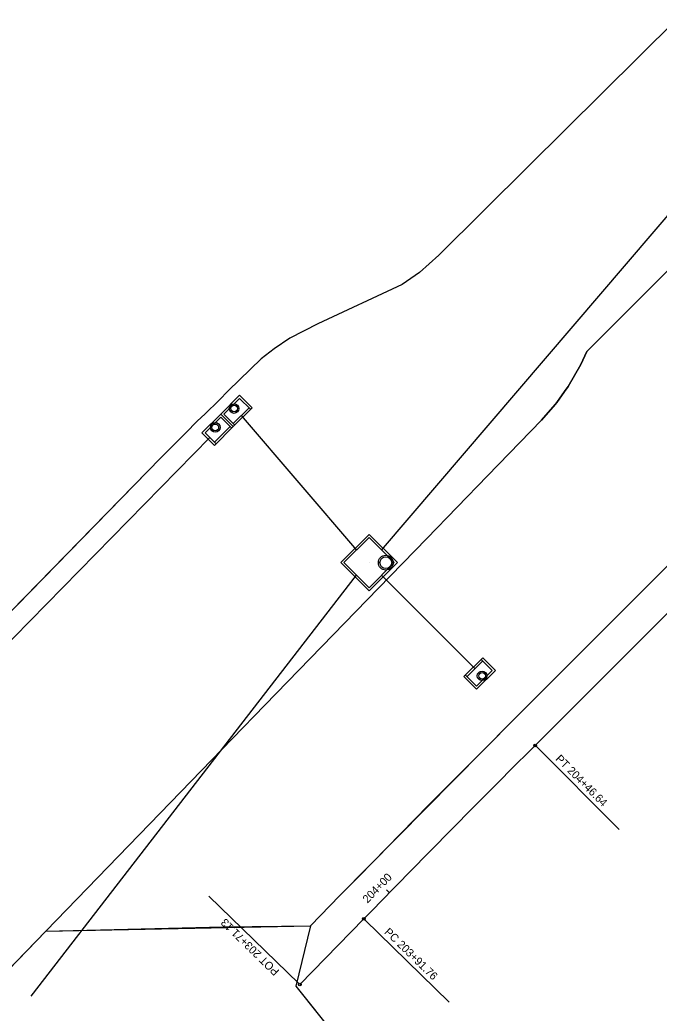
# Model space of a CAD drawing. Extents: x 2251012 to 2259557, y 13786786 to 13792525.
# Drawn here: x 2252898.1 to 2253042, y 13788698.7 to 13788922.1 of the extents above; entities that cross this region are included whole.
import ezdxf

# ---------------------------------------------------------------- set-up
doc = ezdxf.new("R2010")
doc.units = 0
for name, color, linetype in [('D_ALIGN_ANNO_1', 7, 'Continuous'), ('D_BOXES_1', 7, 'Continuous'), ('D_DRAIN_MISC', 7, 'Continuous'), ('D_DRN_AREA_A', 7, 'Continuous'), ('D_DRN_AREA_PHI', 7, 'Continuous'), ('D_DRN_AREA_X', 7, 'Continuous'), ('D_INLET_1', 7, 'Continuous'), ('D_PIPES_1', 7, 'Continuous'), ('Grade_DitchLine', 7, 'Continuous')]:
    doc.layers.add(name, color=color, linetype=linetype)

msp = doc.modelspace()

# ---------------------------------------------------------------- linework, layer by layer
at = {"layer": 'D_ALIGN_ANNO_1'}
for p, q in [((2253014.32, 13788758.7), (2253033.01, 13788739.98)), ((2252981.3, 13788725.76), (2252980.65, 13788726.39)), ((2252960.93, 13788705.3), (2252940.69, 13788725.01)), ((2252975.75, 13788719.65), (2252994.74, 13788701.16))]:
    msp.add_line(p, q, dxfattribs=at)
for centre in [(2253014.11, 13788758.91), (2252975.54, 13788719.86), (2252961.14, 13788705.09)]:
    msp.add_circle(centre, 0.3, dxfattribs=at)
at = {"layer": 'D_BOXES_1'}
for p, q in [((2252979.56, 13788802.85), (2253062.33, 13788899.63)), ((2252900.7, 13788702.47), (2252973.9, 13788797.2))]:
    msp.add_line(p, q, dxfattribs=at)
at = {"layer": 'D_DRAIN_MISC'}
for p, q in [((2252945.82, 13788835.23), (2252945.82, 13788835.23)), ((2252948.65, 13788835.93), (2252948.65, 13788835.93)), ((2252947.94, 13788833.1), (2252947.94, 13788833.1)), ((2252941.58, 13788830.99), (2252941.58, 13788830.99)), ((2252944.76, 13788832.04), (2252944.76, 13788832.04)), ((2252943.7, 13788828.86), (2252943.7, 13788828.86)), ((2252940.87, 13788828.16), (2252940.87, 13788828.16)), ((2252973.9, 13788802.85), (2252973.9, 13788802.85)), ((2252979.56, 13788802.85), (2252979.56, 13788802.85)), ((2252976.73, 13788800.02), (2252976.73, 13788800.02)), ((2252973.9, 13788797.2), (2252973.9, 13788797.2)), ((2252979.56, 13788797.19), (2252979.56, 13788797.19)), ((2253000.58, 13788776.14), (2253000.58, 13788776.14)), ((2253001.64, 13788775.08), (2253001.64, 13788775.08)), ((2253003.41, 13788776.84), (2253003.41, 13788776.84)), ((2252999.87, 13788773.31), (2252999.87, 13788773.31)), ((2253002.7, 13788774.01), (2253002.7, 13788774.01))]:
    msp.add_line(p, q, dxfattribs=at)
at = {"layer": 'D_DRN_AREA_A'}
for p, q in [((2253045.85, 13788922.15), (2253012.64, 13788889.21)), ((2253012.64, 13788889.21), (2252992.46, 13788869.19)), ((2252992.46, 13788869.19), (2252988.07, 13788865.34)), ((2252988.07, 13788865.34), (2252984.21, 13788862.61)), ((2252984.21, 13788862.61), (2252965.2, 13788853.73)), ((2252965.2, 13788853.73), (2252958.91, 13788850.5)), ((2252958.91, 13788850.5), (2252955.35, 13788848.13)), ((2252955.35, 13788848.13), (2252952.47, 13788845.86)), ((2252952.47, 13788845.86), (2252945.11, 13788838.75)), ((2252945.11, 13788838.75), (2252942.89, 13788836.53)), ((2252942.89, 13788836.53), (2252939.85, 13788833.54)), ((2252939.85, 13788833.54), (2252938.06, 13788831.83)), ((2252938.06, 13788831.83), (2252935.45, 13788829.22)), ((2252935.45, 13788829.22), (2252929.84, 13788823.59)), ((2252929.84, 13788823.59), (2252874.02, 13788766.49)), ((2252887.1, 13788699.7), (2252903.98, 13788717.11)), ((2252903.98, 13788717.11), (2252943.92, 13788718.06)), ((2252943.92, 13788718.06), (2252963.58, 13788718.34)), ((2252963.58, 13788718.34), (2252960.26, 13788704.75)), ((2252960.26, 13788704.75), (2252988.05, 13788669.84))]:
    msp.add_line(p, q, dxfattribs=at)
at = {"layer": 'D_DRN_AREA_PHI'}
msp.add_lwpolyline([(2252594.41, 13788488.47), (2252812.73, 13788703.57), (2252703.12, 13788578.79), (2252713.53, 13788568.76), (2252733.51, 13788549.52), (2252848.93, 13788668), (2252863.44, 13788675.31), (2252903.98, 13788717.11), (2252963.58, 13788718.34), (2252960.26, 13788704.75), (2252988.05, 13788669.84), (2253155.91, 13787946.03), (2253227.14, 13787535.53), (2252977.89, 13787289.87), (2252796.09, 13787474.33)], dxfattribs=at)
at = {"layer": 'D_DRN_AREA_X'}
for p, q in [((2253045.85, 13788922.15), (2253012.64, 13788889.21)), ((2253025.74, 13788847.54), (2253047.63, 13788869.4)), ((2253047.63, 13788869.4), (2253025.74, 13788847.54)), ((2253024.38, 13788844.58), (2253025.74, 13788847.54)), ((2253025.74, 13788847.54), (2253024.38, 13788844.58)), ((2253021.56, 13788839.64), (2253024.38, 13788844.58)), ((2253024.38, 13788844.58), (2253021.56, 13788839.64)), ((2253020.76, 13788838.54), (2253021.56, 13788839.64)), ((2253021.56, 13788839.64), (2253020.76, 13788838.54)), ((2253018.99, 13788836.08), (2253020.76, 13788838.54)), ((2253020.76, 13788838.54), (2253018.99, 13788836.08)), ((2253015.52, 13788832.07), (2253018.66, 13788835.63)), ((2253018.66, 13788835.63), (2253015.52, 13788832.07)), ((2253018.66, 13788835.63), (2253018.99, 13788836.08)), ((2253018.99, 13788836.08), (2253018.66, 13788835.63)), ((2253003.36, 13788819.54), (2253015.52, 13788832.07)), ((2253015.52, 13788832.07), (2253003.36, 13788819.54)), ((2252989.7, 13788805.46), (2253003.36, 13788819.54)), ((2253003.36, 13788819.54), (2252989.7, 13788805.46)), ((2252978.83, 13788794.25), (2252989.7, 13788805.46)), ((2252989.7, 13788805.46), (2252978.83, 13788794.25)), ((2252978.83, 13788794.25), (2252953.29, 13788767.93)), ((2252953.29, 13788767.93), (2252946.01, 13788760.43)), ((2252903.98, 13788717.11), (2252946.01, 13788760.43)), ((2252946.01, 13788760.43), (2252903.98, 13788717.11)), ((2252990.18, 13788745.5), (2253003.58, 13788758.93)), ((2252974.41, 13788729.4), (2252990.18, 13788745.5)), ((2252903.98, 13788717.11), (2252943.92, 13788718.06)), ((2252943.92, 13788718.06), (2252963.58, 13788718.34))]:
    msp.add_line(p, q, dxfattribs=at)
for points in [[(2253012.64, 13788889.21), (2252992.46, 13788869.19), (2252988.07, 13788865.34), (2252984.21, 13788862.61), (2252965.2, 13788853.73), (2252958.91, 13788850.5), (2252955.35, 13788848.13), (2252952.47, 13788845.86), (2252945.11, 13788838.75), (2252942.89, 13788836.53), (2252939.85, 13788833.54), (2252938.06, 13788831.83), (2252935.45, 13788829.22), (2252929.84, 13788823.59), (2252874.02, 13788766.49), (2252881.47, 13788764.79), (2252887.1, 13788699.7), (2252903.98, 13788717.11)], [(2253094.09, 13788849.37), (2253090.84, 13788846.12), (2253060.74, 13788816.07), (2253008.83, 13788764.24), (2252970.16, 13788725.1), (2252963.58, 13788718.34)], [(2253003.58, 13788758.93), (2253008.83, 13788764.24), (2253022.74, 13788778.13), (2253045.82, 13788801.17)], [(2252946.01, 13788760.43), (2252953.29, 13788767.93), (2252978.83, 13788794.25)], [(2252963.58, 13788718.34), (2252970.16, 13788725.1), (2252974.41, 13788729.4)], [(2252963.58, 13788718.34), (2252960.26, 13788704.75), (2252988.05, 13788669.84)]]:
    msp.add_lwpolyline(points, dxfattribs=at)
at = {"layer": 'D_INLET_1'}
for p, q in [((2252943.35, 13788833.46), (2252947.59, 13788837.7)), ((2252947.59, 13788837.7), (2252950.42, 13788834.87)), ((2252944.05, 13788833.46), (2252947.59, 13788836.99)), ((2252947.59, 13788836.99), (2252950.07, 13788834.52)), ((2252939.1, 13788829.22), (2252943.35, 13788833.46)), ((2252943.35, 13788833.46), (2252946.17, 13788830.63)), ((2252943.35, 13788833.46), (2252946.17, 13788830.63)), ((2252943.35, 13788833.46), (2252946.17, 13788830.63)), ((2252943.35, 13788833.46), (2252946.17, 13788830.63)), ((2252944.05, 13788833.46), (2252946.53, 13788830.98)), ((2252946.17, 13788830.63), (2252950.42, 13788834.87)), ((2252946.17, 13788831.34), (2252949.71, 13788834.87)), ((2252939.81, 13788829.22), (2252943.35, 13788832.75)), ((2252943.35, 13788832.75), (2252945.82, 13788830.28)), ((2252939.1, 13788829.22), (2252941.93, 13788826.39)), ((2252939.81, 13788829.22), (2252942.28, 13788826.74)), ((2252941.93, 13788826.39), (2252946.17, 13788830.63)), ((2252941.93, 13788827.1), (2252945.47, 13788830.63)), ((2252970.37, 13788800.03), (2252976.74, 13788806.39)), ((2252976.74, 13788806.39), (2252983.1, 13788800.02)), ((2252971.07, 13788800.03), (2252976.74, 13788805.68)), ((2252976.74, 13788805.68), (2252982.39, 13788800.02)), ((2252976.73, 13788793.66), (2252970.37, 13788800.03)), ((2252976.73, 13788794.36), (2252971.07, 13788800.03)), ((2252983.1, 13788800.02), (2252976.73, 13788793.66)), ((2252982.39, 13788800.02), (2252976.73, 13788794.36)), ((2253002.35, 13788778.61), (2252998.1, 13788774.37)), ((2253002.35, 13788777.9), (2252998.81, 13788774.37)), ((2253004.47, 13788775.78), (2253001.99, 13788778.26)), ((2253005.17, 13788775.78), (2253002.35, 13788778.61)), ((2253005.17, 13788775.78), (2253000.93, 13788771.54)), ((2253004.47, 13788775.78), (2253000.93, 13788772.25)), ((2253000.93, 13788771.54), (2252998.1, 13788774.37)), ((2253000.93, 13788772.25), (2252998.45, 13788774.73))]:
    msp.add_line(p, q, dxfattribs=at)
for centre, radius in [((2252946.35, 13788834.69), 1.08), ((2252946.35, 13788834.69), 0.75), ((2252942.11, 13788830.46), 1.08), ((2252942.11, 13788830.46), 0.75), ((2252980.5, 13788800.02), 1.67), ((2252980.5, 13788800.02), 1.33), ((2253002.17, 13788774.55), 1.08), ((2253002.17, 13788774.55), 0.75)]:
    msp.add_circle(centre, radius, dxfattribs=at)
at = {"layer": 'D_PIPES_1'}
for p, q in [((2252947.94, 13788833.1), (2252973.9, 13788802.85)), ((2252879.46, 13788765.62), (2252940.87, 13788828.16)), ((2253000.58, 13788776.14), (2252979.56, 13788797.19))]:
    msp.add_line(p, q, dxfattribs=at)
at = {"layer": 'Grade_DitchLine'}
for p, q in [((2253014.11, 13788758.91), (2253101.01, 13788845.67)), ((2252961.14, 13788705.09), (2252975.54, 13788719.86))]:
    msp.add_line(p, q, dxfattribs=at)
msp.add_arc((2255801.75, 13785966.77), 3945.5, 134.95375, 135.75083, dxfattribs=at)

# ---------------------------------------------------------------- texts
at = {"layer": 'D_ALIGN_ANNO_1'}
for s, rotation, p in [('PT 204+46.64', 314.9537, (2253018.56, 13788755.73)), ('204+00', 45.6311, (2252976.37, 13788723.3)), ('POT 203+71.13', 135.7508, (2252956.65, 13788708.21)), ('PC 203+91.76', 315.7508, (2252980.03, 13788716.74))]:
    msp.add_text(s, height=1.8, rotation=rotation, dxfattribs=at).set_placement(p)

doc.saveas('drawing.dxf')
